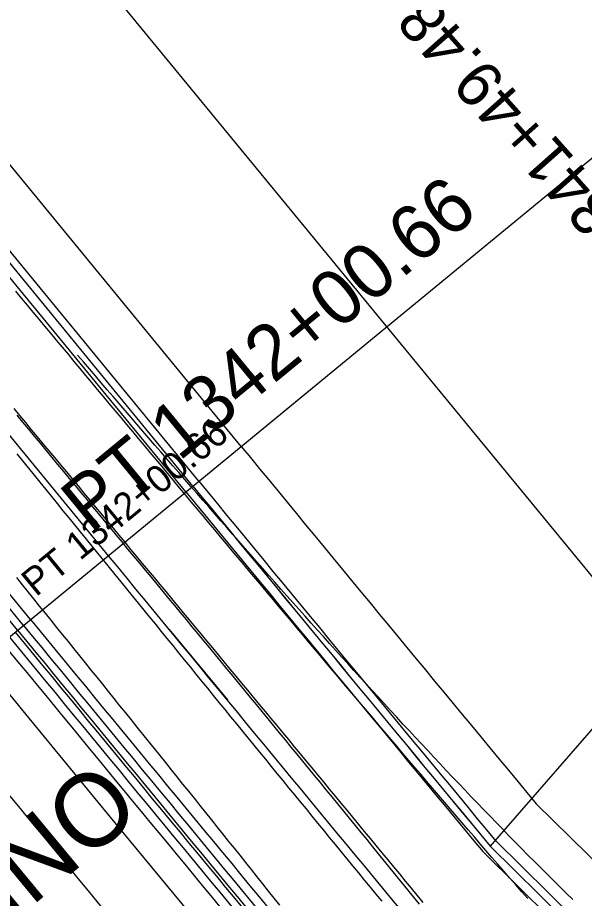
# Model space of a CAD drawing. Extents: x 2252205 to 2259955, y 13788514 to 13798103.
# Drawn here: x 2256270.5 to 2256332.5, y 13792366.9 to 13792463.2 of the extents above; entities that cross this region are included whole.
import ezdxf

# ---------------------------------------------------------------- set-up
doc = ezdxf.new("R2010")
doc.units = 0
for name, color, linetype in [('D_RDWY_TRACK_BUS', 7, 'Continuous'), ('D_RDWY_TRACK_TRUCK_WB62', 7, 'Continuous'), ('GEOM_CENTERLINE_ALIGN', 7, 'Continuous'), ('GEOM_CENTERLINE_PCPT_100', 7, 'Continuous'), ('GEOM_CENTERLINE_PCPT_50', 7, 'Continuous'), ('Road_Curb_Back', 7, 'Continuous'), ('Road_Curb_Face', 7, 'Continuous'), ('Road_EdgeOfPavementInside', 7, 'Continuous'), ('Road_EdgeOfPavementOutside', 7, 'Continuous'), ('ROAD_ROW_EXIST', 7, 'Continuous'), ('ROAD_SCRATCH_EP_CONTROL', 7, 'Continuous'), ('Road_Sidewalk_Back', 7, 'Continuous'), ('TRAF_PAVMRK_W_4IN_BRK', 7, 'Continuous'), ('TRAF_PAVMRK_W_4IN_SLD', 7, 'Continuous'), ('TRAF_PAVMRK_W_8IN_SLD', 7, 'Continuous'), ('TRAF_PAVMRK_W_LT_TRN_ARROW_WORD', 7, 'Continuous'), ('TRAF_PAVMRK_Y_4IN_SLD', 7, 'Continuous')]:
    doc.layers.add(name, color=color, linetype=linetype)

msp = doc.modelspace()

# ---------------------------------------------------------------- linework, layer by layer
at = {"layer": 'D_RDWY_TRACK_BUS'}
for points in [[(2256326.269, 13792366.861), (2256325.615, 13792367.611), (2256324.961, 13792368.363), (2256324.307, 13792369.115), (2256323.654, 13792369.867), (2256323.002, 13792370.621), (2256322.35, 13792371.375), (2256321.699, 13792372.129), (2256321.047, 13792372.884), (2256320.397, 13792373.64), (2256319.747, 13792374.396), (2256319.097, 13792375.152), (2256318.448, 13792375.91), (2256317.799, 13792376.667), (2256317.15, 13792377.425), (2256316.502, 13792378.183), (2256315.854, 13792378.942), (2256315.206, 13792379.701), (2256314.559, 13792380.461), (2256313.912, 13792381.22), (2256313.265, 13792381.981), (2256312.618, 13792382.741), (2256311.972, 13792383.502), (2256311.326, 13792384.263), (2256310.68, 13792385.025), (2256310.035, 13792385.786), (2256309.39, 13792386.548), (2256308.745, 13792387.311), (2256308.1, 13792388.073), (2256307.455, 13792388.836), (2256306.811, 13792389.599), (2256306.167, 13792390.362), (2256305.523, 13792391.126), (2256304.879, 13792391.889), (2256304.235, 13792392.653), (2256303.592, 13792393.417), (2256302.949, 13792394.182), (2256302.305, 13792394.946), (2256301.662, 13792395.711), (2256301.02, 13792396.475), (2256300.377, 13792397.24), (2256299.734, 13792398.005), (2256299.092, 13792398.771), (2256298.449, 13792399.536), (2256297.807, 13792400.302), (2256297.165, 13792401.067), (2256296.523, 13792401.833), (2256295.881, 13792402.599), (2256295.239, 13792403.365), (2256294.598, 13792404.131), (2256293.956, 13792404.897), (2256293.314, 13792405.664), (2256292.673, 13792406.43), (2256292.032, 13792407.197), (2256291.39, 13792407.963), (2256290.749, 13792408.73), (2256290.108, 13792409.497), (2256289.467, 13792410.264), (2256288.826, 13792411.031), (2256288.185, 13792411.798), (2256287.544, 13792412.565), (2256286.904, 13792413.332), (2256286.263, 13792414.099), (2256285.622, 13792414.867), (2256284.982, 13792415.634), (2256284.341, 13792416.402), (2256283.701, 13792417.169), (2256283.06, 13792417.937), (2256282.42, 13792418.704), (2256281.779, 13792419.472), (2256281.139, 13792420.24), (2256280.499, 13792421.008), (2256279.859, 13792421.776), (2256279.218, 13792422.543), (2256278.578, 13792423.311), (2256277.938, 13792424.079), (2256277.298, 13792424.847), (2256276.658, 13792425.615), (2256276.018, 13792426.384), (2256275.378, 13792427.152), (2256274.738, 13792427.92), (2256274.098, 13792428.688), (2256273.458, 13792429.456), (2256272.819, 13792430.225), (2256272.179, 13792430.993), (2256271.539, 13792431.761), (2256270.899, 13792432.53), (2256270.259, 13792433.298)], [(2256314.414, 13792366.266), (2256313.779, 13792367.051), (2256313.143, 13792367.836), (2256312.507, 13792368.62), (2256311.871, 13792369.404), (2256311.235, 13792370.187), (2256310.598, 13792370.97), (2256309.962, 13792371.752), (2256309.326, 13792372.533), (2256308.689, 13792373.314), (2256308.053, 13792374.095), (2256307.416, 13792374.875), (2256306.779, 13792375.655), (2256306.142, 13792376.435), (2256305.506, 13792377.214), (2256304.869, 13792377.992), (2256304.232, 13792378.771), (2256303.594, 13792379.549), (2256302.957, 13792380.326), (2256302.32, 13792381.104), (2256301.683, 13792381.881), (2256301.046, 13792382.657), (2256300.408, 13792383.434), (2256299.771, 13792384.21), (2256299.133, 13792384.986), (2256298.496, 13792385.761), (2256297.858, 13792386.537), (2256297.22, 13792387.312), (2256296.583, 13792388.087), (2256295.945, 13792388.862), (2256295.307, 13792389.636), (2256294.669, 13792390.411), (2256294.031, 13792391.185), (2256293.393, 13792391.959), (2256292.756, 13792392.732), (2256292.118, 13792393.506), (2256291.479, 13792394.279), (2256290.841, 13792395.053), (2256290.203, 13792395.826), (2256289.565, 13792396.599), (2256288.927, 13792397.371), (2256288.289, 13792398.144), (2256287.65, 13792398.917), (2256287.012, 13792399.689), (2256286.374, 13792400.461), (2256285.735, 13792401.234), (2256285.097, 13792402.006), (2256284.459, 13792402.778), (2256283.82, 13792403.549), (2256283.182, 13792404.321), (2256282.543, 13792405.093), (2256281.905, 13792405.864), (2256281.266, 13792406.636), (2256280.628, 13792407.407), (2256279.989, 13792408.178), (2256279.351, 13792408.95), (2256278.712, 13792409.721), (2256278.073, 13792410.492), (2256277.435, 13792411.263), (2256276.796, 13792412.034), (2256276.157, 13792412.804), (2256275.519, 13792413.575), (2256274.88, 13792414.346), (2256274.241, 13792415.117), (2256273.602, 13792415.887), (2256272.964, 13792416.658), (2256272.325, 13792417.428), (2256271.686, 13792418.199), (2256271.047, 13792418.969), (2256270.409, 13792419.739)], [(2256310.345, 13792366.569), (2256309.705, 13792367.345), (2256309.065, 13792368.122), (2256308.426, 13792368.898), (2256307.787, 13792369.675), (2256307.149, 13792370.451), (2256306.51, 13792371.228), (2256305.872, 13792372.004), (2256305.235, 13792372.781), (2256304.597, 13792373.558), (2256303.96, 13792374.334), (2256303.323, 13792375.111), (2256302.687, 13792375.887), (2256302.051, 13792376.664), (2256301.415, 13792377.44), (2256300.779, 13792378.217), (2256300.143, 13792378.994), (2256299.508, 13792379.77), (2256298.873, 13792380.547), (2256298.238, 13792381.323), (2256297.603, 13792382.1), (2256296.968, 13792382.877), (2256296.334, 13792383.653), (2256295.7, 13792384.43), (2256295.066, 13792385.207), (2256294.432, 13792385.983), (2256293.798, 13792386.76), (2256293.165, 13792387.536), (2256292.531, 13792388.313), (2256291.898, 13792389.09), (2256291.265, 13792389.866), (2256290.632, 13792390.643), (2256289.999, 13792391.42), (2256289.366, 13792392.196), (2256288.733, 13792392.973), (2256288.101, 13792393.75), (2256287.468, 13792394.527), (2256286.836, 13792395.303), (2256286.204, 13792396.08), (2256285.572, 13792396.857), (2256284.94, 13792397.633), (2256284.308, 13792398.41), (2256283.676, 13792399.187), (2256283.044, 13792399.963), (2256282.412, 13792400.74), (2256281.78, 13792401.517), (2256281.149, 13792402.294), (2256280.517, 13792403.07), (2256279.886, 13792403.847), (2256279.255, 13792404.624), (2256278.623, 13792405.401), (2256277.992, 13792406.177), (2256277.361, 13792406.954), (2256276.73, 13792407.731), (2256276.099, 13792408.508), (2256275.467, 13792409.284), (2256274.837, 13792410.061), (2256274.206, 13792410.838), (2256273.575, 13792411.615), (2256272.944, 13792412.392), (2256272.313, 13792413.168), (2256271.682, 13792413.945), (2256271.052, 13792414.722), (2256270.421, 13792415.499)], [(2256299.163, 13792366.135), (2256298.541, 13792366.916), (2256297.919, 13792367.697), (2256297.296, 13792368.478), (2256296.673, 13792369.259), (2256296.05, 13792370.04), (2256295.427, 13792370.82), (2256294.803, 13792371.6), (2256294.179, 13792372.38), (2256293.555, 13792373.161), (2256292.931, 13792373.94), (2256292.306, 13792374.72), (2256291.682, 13792375.5), (2256291.057, 13792376.28), (2256290.432, 13792377.059), (2256289.807, 13792377.839), (2256289.181, 13792378.618), (2256288.556, 13792379.397), (2256287.93, 13792380.176), (2256287.304, 13792380.955), (2256286.678, 13792381.734), (2256286.052, 13792382.513), (2256285.426, 13792383.292), (2256284.8, 13792384.071), (2256284.173, 13792384.849), (2256283.547, 13792385.628), (2256282.92, 13792386.407), (2256282.293, 13792387.185), (2256281.666, 13792387.963), (2256281.039, 13792388.742), (2256280.412, 13792389.52), (2256279.785, 13792390.298), (2256279.158, 13792391.077), (2256278.53, 13792391.855), (2256277.903, 13792392.633), (2256277.275, 13792393.411), (2256276.647, 13792394.189), (2256276.02, 13792394.967), (2256275.392, 13792395.745), (2256274.764, 13792396.523), (2256274.136, 13792397.301), (2256273.508, 13792398.078), (2256272.88, 13792398.856), (2256272.252, 13792399.634), (2256271.624, 13792400.412), (2256270.995, 13792401.189), (2256270.367, 13792401.967)]]:
    msp.add_lwpolyline(points, dxfattribs=at)
at = {"layer": 'D_RDWY_TRACK_TRUCK_WB62'}
for points in [[(2256331.191, 13792366.762), (2256330.488, 13792367.451), (2256329.786, 13792368.143), (2256329.086, 13792368.836), (2256328.387, 13792369.532), (2256327.689, 13792370.229), (2256326.993, 13792370.928), (2256326.298, 13792371.629), (2256325.604, 13792372.332), (2256324.911, 13792373.036), (2256324.219, 13792373.742), (2256323.529, 13792374.449), (2256322.839, 13792375.159), (2256322.151, 13792375.869), (2256321.464, 13792376.581), (2256320.778, 13792377.295), (2256320.092, 13792378.01), (2256319.408, 13792378.726), (2256318.725, 13792379.444), (2256318.043, 13792380.163), (2256317.362, 13792380.883), (2256316.682, 13792381.605), (2256316.003, 13792382.328), (2256315.324, 13792383.052), (2256314.647, 13792383.777), (2256313.97, 13792384.503), (2256313.294, 13792385.23), (2256312.619, 13792385.958), (2256311.945, 13792386.688), (2256311.272, 13792387.418), (2256310.599, 13792388.149), (2256309.927, 13792388.882), (2256309.256, 13792389.615), (2256308.586, 13792390.349), (2256307.916, 13792391.084), (2256307.247, 13792391.82), (2256306.579, 13792392.556), (2256305.912, 13792393.294), (2256305.245, 13792394.032), (2256304.579, 13792394.771), (2256303.913, 13792395.511), (2256303.248, 13792396.251), (2256302.584, 13792396.992), (2256301.92, 13792397.734), (2256301.257, 13792398.477), (2256300.594, 13792399.22), (2256299.932, 13792399.964), (2256299.27, 13792400.709), (2256298.609, 13792401.454), (2256297.949, 13792402.2), (2256297.288, 13792402.946), (2256296.629, 13792403.693), (2256295.97, 13792404.44), (2256295.311, 13792405.188), (2256294.653, 13792405.937), (2256293.995, 13792406.686), (2256293.338, 13792407.435), (2256292.681, 13792408.185), (2256292.025, 13792408.936), (2256291.369, 13792409.687), (2256290.713, 13792410.438), (2256290.058, 13792411.19), (2256289.403, 13792411.942), (2256288.749, 13792412.695), (2256288.095, 13792413.448), (2256287.441, 13792414.201), (2256286.788, 13792414.955), (2256286.135, 13792415.709), (2256285.482, 13792416.464), (2256284.829, 13792417.219), (2256284.177, 13792417.974), (2256283.526, 13792418.73), (2256282.874, 13792419.486), (2256282.223, 13792420.242), (2256281.572, 13792420.999), (2256280.921, 13792421.756), (2256280.271, 13792422.513), (2256279.621, 13792423.271), (2256278.971, 13792424.029), (2256278.322, 13792424.787), (2256277.672, 13792425.545), (2256277.023, 13792426.304)], [(2256314.818, 13792366.453), (2256314.179, 13792367.229), (2256313.54, 13792368.005), (2256312.901, 13792368.781), (2256312.262, 13792369.557), (2256311.623, 13792370.332), (2256310.985, 13792371.107), (2256310.346, 13792371.882), (2256309.707, 13792372.657), (2256309.068, 13792373.431), (2256308.429, 13792374.205), (2256307.79, 13792374.979), (2256307.151, 13792375.753), (2256306.512, 13792376.526), (2256305.873, 13792377.299), (2256305.234, 13792378.072), (2256304.595, 13792378.845), (2256303.956, 13792379.618), (2256303.317, 13792380.39), (2256302.678, 13792381.163), (2256302.039, 13792381.935), (2256301.4, 13792382.707), (2256300.761, 13792383.479), (2256300.122, 13792384.251), (2256299.483, 13792385.022), (2256298.844, 13792385.794), (2256298.205, 13792386.565), (2256297.566, 13792387.337), (2256296.927, 13792388.108), (2256296.288, 13792388.879), (2256295.649, 13792389.65), (2256295.01, 13792390.421), (2256294.371, 13792391.192), (2256293.732, 13792391.963), (2256293.093, 13792392.734), (2256292.454, 13792393.504), (2256291.815, 13792394.275), (2256291.176, 13792395.045), (2256290.537, 13792395.816), (2256289.898, 13792396.586), (2256289.259, 13792397.356), (2256288.62, 13792398.127), (2256287.981, 13792398.897), (2256287.342, 13792399.667), (2256286.703, 13792400.437), (2256286.064, 13792401.207), (2256285.424, 13792401.977), (2256284.785, 13792402.747), (2256284.146, 13792403.517), (2256283.507, 13792404.287), (2256282.868, 13792405.057), (2256282.229, 13792405.827), (2256281.59, 13792406.597), (2256280.951, 13792407.366), (2256280.312, 13792408.136), (2256279.673, 13792408.906), (2256279.034, 13792409.676), (2256278.394, 13792410.445), (2256277.755, 13792411.215), (2256277.116, 13792411.985), (2256276.477, 13792412.754), (2256275.838, 13792413.524), (2256275.199, 13792414.293), (2256274.56, 13792415.063), (2256273.921, 13792415.832), (2256273.282, 13792416.602), (2256272.643, 13792417.371), (2256272.003, 13792418.141), (2256271.364, 13792418.91), (2256270.725, 13792419.679), (2256270.086, 13792420.449)]]:
    msp.add_lwpolyline(points, dxfattribs=at)
at = {"layer": 'GEOM_CENTERLINE_ALIGN'}
msp.add_arc((2265118.999, 13799669.27), 11459.16, 219.4185534, 224.3273853, dxfattribs=at)
at = {"layer": 'GEOM_CENTERLINE_PCPT_100'}
msp.add_line((2256267.249, 13792393.559), (2256340.138, 13792453.47), dxfattribs=at)
at = {"layer": 'GEOM_CENTERLINE_PCPT_50'}
msp.add_line((2256266.863, 13792393.242), (2256303.307, 13792423.197), dxfattribs=at)
at = {"layer": 'Road_Curb_Back'}
for p, q in [((2256290.296, 13792412.503), (2256064.176, 13792687.604)), ((2256270.468, 13792396.205), (2256080.395, 13792627.451)), ((2256322.768, 13792373.176), (2256365.74, 13792330.957))]:
    msp.add_line(p, q, dxfattribs=at)
for radius, end in [(11428.327, 219.6744164), (11453.993, 219.921869), (11454.327, 219.921869)]:
    msp.add_arc((2265118.999, 13799669.27), radius, 219.4185534, end, dxfattribs=at)
at = {"layer": 'Road_Curb_Face'}
for p, q in [((2256289.653, 13792411.974), (2256063.577, 13792687.021)), ((2256322.154, 13792372.611), (2256365.156, 13792330.363))]:
    msp.add_line(p, q, dxfattribs=at)
for radius, end in [(11429.16, 219.6744164), (11500.16, 219.8232636)]:
    msp.add_arc((2265118.999, 13799669.27), radius, 219.4185534, end, dxfattribs=at)
at = {"layer": 'Road_EdgeOfPavementInside'}
msp.add_line((2256271.112, 13792396.734), (2256081.039, 13792627.98), dxfattribs=at)
for radius in [11453.16, 11455.16]:
    msp.add_arc((2265118.999, 13799669.27), radius, 219.4185534, 219.921869, dxfattribs=at)
at = {"layer": 'Road_EdgeOfPavementOutside'}
for p, q in [((2256289.653, 13792411.974), (2256063.577, 13792687.021)), ((2256365.156, 13792330.363), (2256322.154, 13792372.611))]:
    msp.add_line(p, q, dxfattribs=at)
msp.add_arc((2265118.999, 13799669.27), 11429.16, 219.4185534, 219.6744553, dxfattribs=at)
at = {"layer": 'ROAD_ROW_EXIST'}
msp.add_line((2256083.312, 13792706.205), (2256400.161, 13792320.718), dxfattribs=at)
at = {"layer": 'ROAD_SCRATCH_EP_CONTROL'}
msp.add_lwpolyline([(2256353.866, 13792418.837), (2256358.196, 13792413.956), (2256322.154, 13792372.611)], dxfattribs=at)
at = {"layer": 'Road_Sidewalk_Back'}
for p, q in [((2256294.931, 13792416.313), (2256068.494, 13792691.801)), ((2256327.191, 13792377.242), (2256357.7, 13792347.268))]:
    msp.add_line(p, q, dxfattribs=at)
msp.add_arc((2265118.999, 13799669.27), 11422.327, 219.4185534, 219.6727095, dxfattribs=at)
at = {"layer": 'TRAF_PAVMRK_W_4IN_BRK'}
msp.add_line((2256052.59, 13792681.49), (2256280.382, 13792404.354), dxfattribs=at)
for points in [[(2256293.459, 13792388.586), (2256287.075, 13792396.283)], [(2256293.465, 13792388.578), (2256293.459, 13792388.586)]]:
    msp.add_lwpolyline(points, dxfattribs=at)
for radius, end in [(11441.16, 219.921869), (11477.16, 219.8969182)]:
    msp.add_arc((2265118.999, 13799669.27), radius, 219.4185534, end, dxfattribs=at)
at = {"layer": 'TRAF_PAVMRK_W_4IN_SLD'}
for p, q in [((2256288.88, 13792411.339), (2256061.078, 13792688.487)), ((2256321.417, 13792371.934), (2256364.456, 13792329.649))]:
    msp.add_line(p, q, dxfattribs=at)
for radius, end in [(11430.16, 219.6744553), (11499.16, 219.8232636)]:
    msp.add_arc((2265118.999, 13799669.27), radius, 219.4185534, end, dxfattribs=at)
at = {"layer": 'TRAF_PAVMRK_W_8IN_SLD'}
for radius, end in [(11466.16, 219.8968895), (11488.16, 219.8969469)]:
    msp.add_arc((2265118.999, 13799669.27), radius, 219.4185534, end, dxfattribs=at)
at = {"layer": 'TRAF_PAVMRK_Y_4IN_SLD'}
msp.add_line((2256271.884, 13792397.369), (2256044.102, 13792674.493), dxfattribs=at)
for radius, end in [(11452.16, 219.921869), (11456.16, 219.8968633)]:
    msp.add_arc((2265118.999, 13799669.27), radius, 219.4185534, end, dxfattribs=at)

# ---------------------------------------------------------------- texts
at = {"layer": 'GEOM_CENTERLINE_PCPT_100'}
msp.add_text('PT 1342+00.66', height=6, rotation=39.41855, dxfattribs=at).set_placement((2256278.477, 13792406.671))
at = {"layer": 'GEOM_CENTERLINE_PCPT_50'}
msp.add_text('PT 1342+00.66', height=3, rotation=39.41855, dxfattribs=at).set_placement((2256272.477, 13792399.798))
at = {"layer": 'ROAD_SCRATCH_EP_CONTROL'}
msp.add_text('CL STA 1341+49.48', height=5, rotation=131.57831, dxfattribs=at).set_placement((2256355.735, 13792420.497))
at = {"layer": 'TRAF_PAVMRK_W_LT_TRN_ARROW_WORD'}
msp.add_text('ONLY', height=8, rotation=219.65869, dxfattribs=at).set_placement((2256279.177, 13792382.317))

doc.saveas('drawing.dxf')
